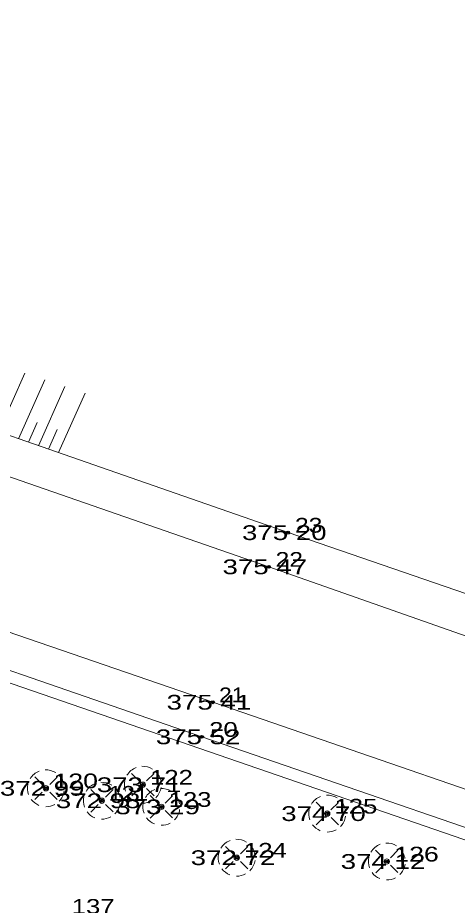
# Model space of a CAD drawing. Extents: x -789669 to -789458, y -977587 to -977420.
# Drawn here: x -789595.52 to -789574.69, y -977462.39 to -977420.32 of the extents above; entities that cross this region are included whole.
import ezdxf
from ezdxf.enums import TextEntityAlignment as Align

# ---------------------------------------------------------------- set-up
doc = ezdxf.new("R2010")
doc.units = 0
doc.header["$LTSCALE"] = 0.28
doc.header["$PDMODE"] = 32
doc.header["$PDSIZE"] = 0.14
for name, color, linetype, lineweight in [('1', 7, 'Continuous', 13), ('2', 7, 'Continuous', 13), ('3', 7, 'Continuous', 13), ('4', 7, 'Continuous', 13)]:
    doc.layers.add(name, color=color, linetype=linetype, lineweight=lineweight)
for name, color, linetype in [('57', 7, 'Continuous'), ('58', 7, 'Continuous'), ('59', 7, 'Continuous')]:
    doc.layers.add(name, color=color, linetype=linetype)

msp = doc.modelspace()

# ---------------------------------------------------------------- linework, layer by layer
at = {"layer": '1'}
for points in [[(-789652.33, -977422.61), (-789627.98, -977430.97), (-789609.02, -977437.54), (-789583.63, -977446.35), (-789563.97, -977453.25), (-789542.04, -977460.63), (-789524.21, -977466.84), (-789507.23, -977472.64), (-789487.17, -977479.36)], [(-789509.64, -977479.12), (-789526.32, -977473.4), (-789544.78, -977467.07), (-789566.2, -977459.68), (-789586.28, -977452.77), (-789604.78, -977446.41), (-789630.61, -977437.53), (-789654.9, -977429.37)], [(-789604.26, -977448.38), (-789586.79, -977454.41), (-789566.59, -977461.37), (-789545.35, -977468.71), (-789526.33, -977475.15), (-789510.21, -977480.66), (-789489.34, -977487.73), (-789463.94, -977496.44)]]:
    msp.add_lwpolyline(points, dxfattribs=at)
at = {"layer": '2'}
for p, q in [((-789596.44, -977439.947), (-789595.191, -977437.164)), ((-789595.492, -977440.277), (-789594.237, -977437.482)), ((-789594.544, -977440.607), (-789593.284, -977437.8)), ((-789593.596, -977440.937), (-789592.331, -977438.118)), ((-789595.018, -977440.442), (-789594.599, -977439.509)), ((-789594.07, -977440.772), (-789593.65, -977439.836))]:
    msp.add_line(p, q, dxfattribs=at)
msp.add_lwpolyline([(-789651.99, -977420.32), (-789627.42, -977429.7), (-789608.58, -977435.72), (-789582.71, -977444.73), (-789563.37, -977451.38), (-789541.29, -977458.45), (-789523.64, -977464.38), (-789506.63, -977471.11), (-789487.17, -977479.36)], dxfattribs=at)
at = {"layer": '3'}
msp.add_lwpolyline([(-789601.84, -977457.06), (-789598.55, -977450.95), (-789566.5, -977461.99), (-789545.47, -977469.2), (-789526.54, -977475.63), (-789520.95, -977477.5)], dxfattribs=at)
at = {"layer": '4'}
for p, q in [((-789594.714, -977456.312), (-789594.357, -977456.668)), ((-789593.654, -977456.32), (-789594.007, -977456.673)), ((-789590.124, -977456.142), (-789589.767, -977456.498)), ((-789589.064, -977456.15), (-789589.417, -977456.503)), ((-789594.18, -977456.856), (-789594.18, -977456.844)), ((-789590.12, -977457.213), (-789589.768, -977456.862)), ((-789589.59, -977456.686), (-789589.59, -977456.674)), ((-789589.416, -977456.857), (-789589.064, -977457.207)), ((-789594.71, -977457.383), (-789594.358, -977457.032)), ((-789594.006, -977457.027), (-789593.654, -977457.377)), ((-789592.064, -977456.902), (-789591.707, -977457.258)), ((-789591.004, -977456.91), (-789591.357, -977457.263)), ((-789589.244, -977457.192), (-789588.887, -977457.548)), ((-789588.184, -977457.2), (-789588.537, -977457.553)), ((-789592.06, -977457.973), (-789591.708, -977457.622)), ((-789591.53, -977457.446), (-789591.53, -977457.434)), ((-789591.356, -977457.617), (-789591.004, -977457.967)), ((-789588.71, -977457.736), (-789588.71, -977457.724)), ((-789581.384, -977457.512), (-789581.027, -977457.868)), ((-789580.324, -977457.52), (-789580.677, -977457.873)), ((-789589.24, -977458.263), (-789588.888, -977457.912)), ((-789588.536, -977457.907), (-789588.184, -977458.257)), ((-789580.85, -977458.056), (-789580.85, -977458.044)), ((-789581.38, -977458.583), (-789581.028, -977458.232)), ((-789580.676, -977458.227), (-789580.324, -977458.577)), ((-789585.674, -977459.602), (-789585.317, -977459.958)), ((-789584.614, -977459.61), (-789584.967, -977459.963)), ((-789578.564, -977459.782), (-789578.207, -977460.138)), ((-789577.504, -977459.79), (-789577.857, -977460.143)), ((-789585.14, -977460.146), (-789585.14, -977460.134)), ((-789585.67, -977460.673), (-789585.318, -977460.322)), ((-789584.966, -977460.317), (-789584.614, -977460.667)), ((-789578.56, -977460.853), (-789578.208, -977460.502)), ((-789578.03, -977460.326), (-789578.03, -977460.314)), ((-789577.856, -977460.497), (-789577.504, -977460.847))]:
    msp.add_line(p, q, dxfattribs=at)
for centre in [(-789594.1839, -977456.8494), (-789589.5939, -977456.6794), (-789591.5339, -977457.4394), (-789588.7139, -977457.7294), (-789580.8539, -977458.0494), (-789585.1439, -977460.1394), (-789578.0339, -977460.3194)]:
    msp.add_circle(centre, 0.125, dxfattribs=at)
for centre, start, end in [((-789594.1839, -977456.8494), 111.04924, 149.34666), ((-789594.1839, -977456.8494), 57.94289, 92.85253), ((-789589.5939, -977456.6794), 111.04924, 149.34666), ((-789589.5939, -977456.6794), 57.94289, 92.85253), ((-789594.1839, -977456.8494), 9.68453, 44.47714), ((-789589.5939, -977456.6794), 9.68453, 44.47714), ((-789594.1839, -977456.8494), 166.76695, 200.11735), ((-789591.5339, -977457.4394), 111.04924, 149.34666), ((-789591.5339, -977457.4394), 57.94289, 92.85253), ((-789591.5339, -977457.4394), 9.68453, 44.47714), ((-789589.5939, -977456.6794), 166.76695, 200.11735), ((-789589.5939, -977456.6794), 315.09105, 351.67435), ((-789588.7139, -977457.7294), 57.94289, 92.85253), ((-789594.1839, -977456.8494), 315.09105, 351.67435), ((-789591.5339, -977457.4394), 166.76695, 200.11735), ((-789589.5939, -977456.6794), 217.06959, 247.69959), ((-789588.7139, -977457.7294), 111.04924, 149.34666), ((-789588.7139, -977457.7294), 9.68453, 44.47714), ((-789580.8539, -977458.0494), 111.04924, 149.34666), ((-789580.8539, -977458.0494), 57.94289, 92.85253), ((-789594.1839, -977456.8494), 217.06959, 247.69959), ((-789594.1839, -977456.8494), 269.18965, 298.56841), ((-789591.5339, -977457.4394), 315.09105, 351.67435), ((-789589.5939, -977456.6794), 269.18965, 298.56841), ((-789588.7139, -977457.7294), 166.76695, 200.11735), ((-789580.8539, -977458.0494), 9.68453, 44.47714), ((-789591.5339, -977457.4394), 217.06959, 247.69959), ((-789588.7139, -977457.7294), 315.09105, 351.67435), ((-789580.8539, -977458.0494), 166.76695, 200.11735), ((-789591.5339, -977457.4394), 269.18965, 298.56841), ((-789588.7139, -977457.7294), 217.06959, 247.69959), ((-789588.7139, -977457.7294), 269.18965, 298.56841), ((-789580.8539, -977458.0494), 217.06959, 247.69959), ((-789580.8539, -977458.0494), 315.09105, 351.67435), ((-789580.8539, -977458.0494), 269.18965, 298.56841), ((-789585.1439, -977460.1394), 111.04924, 149.34666), ((-789585.1439, -977460.1394), 57.94289, 92.85253), ((-789585.1439, -977460.1394), 9.68453, 44.47714), ((-789578.0339, -977460.3194), 111.04924, 149.34666), ((-789578.0339, -977460.3194), 57.94289, 92.85253), ((-789578.0339, -977460.3194), 9.68453, 44.47714), ((-789585.1439, -977460.1394), 166.76695, 200.11735), ((-789578.0339, -977460.3194), 166.76695, 200.11735), ((-789585.1439, -977460.1394), 217.06959, 247.69959), ((-789585.1439, -977460.1394), 315.09105, 351.67435), ((-789578.0339, -977460.3194), 315.09105, 351.67435), ((-789585.1439, -977460.1394), 269.18965, 298.56841), ((-789578.0339, -977460.3194), 217.06959, 247.69959), ((-789578.0339, -977460.3194), 269.18965, 298.56841)]:
    msp.add_arc(centre, 0.875, start, end, dxfattribs=at)
at = {"layer": '57'}
for p in [(-789582.71, -977444.73), (-789583.63, -977446.35), (-789586.28, -977452.77), (-789586.79, -977454.41), (-789594.18, -977456.85), (-789589.59, -977456.68), (-789591.53, -977457.44), (-789588.71, -977457.73), (-789580.85, -977458.05), (-789585.14, -977460.14), (-789578.03, -977460.32)]:
    msp.add_point(p, dxfattribs=at)

# ---------------------------------------------------------------- texts
at = {"layer": '58'}
for s, width, p in [(' 23', 1.25, (-789582.71, -977444.73)), (' 22', 1.25, (-789583.63, -977446.35)), (' 21', 1.15, (-789586.28, -977452.77)), (' 20', 1.3, (-789586.79, -977454.41)), (' 122', 1.3, (-789589.59, -977456.68)), (' 120', 1.35, (-789594.18, -977456.85)), (' 121', 1.2, (-789591.53, -977457.44)), (' 123', 1.3, (-789588.71, -977457.73)), (' 125', 1.3, (-789580.85, -977458.05)), (' 124', 1.3, (-789585.14, -977460.14)), (' 126', 1.35, (-789578.03, -977460.32)), (' 137', 1.3, (-789593.3, -977462.8))]:
    msp.add_text(s, height=0.7, dxfattribs=dict(at, width=width)).set_placement(p)
at = {"layer": '59', "width": 1.4}
for s, p in [('375 20 ', (-789582.71, -977445.08)), ('375 47 ', (-789583.63, -977446.7)), ('375 41 ', (-789586.28, -977453.12)), ('375 52 ', (-789586.79, -977454.76)), ('373 71 ', (-789589.59, -977457.03)), ('372 99 ', (-789594.18, -977457.2)), ('372 98 ', (-789591.53, -977457.79)), ('373 29 ', (-789588.71, -977458.08)), ('374 70 ', (-789580.85, -977458.4)), ('372 72 ', (-789585.14, -977460.49)), ('374 12 ', (-789578.03, -977460.67))]:
    msp.add_text(s, height=0.7, dxfattribs=at).set_placement(p, align=Align.CENTER)

doc.saveas('drawing.dxf')
